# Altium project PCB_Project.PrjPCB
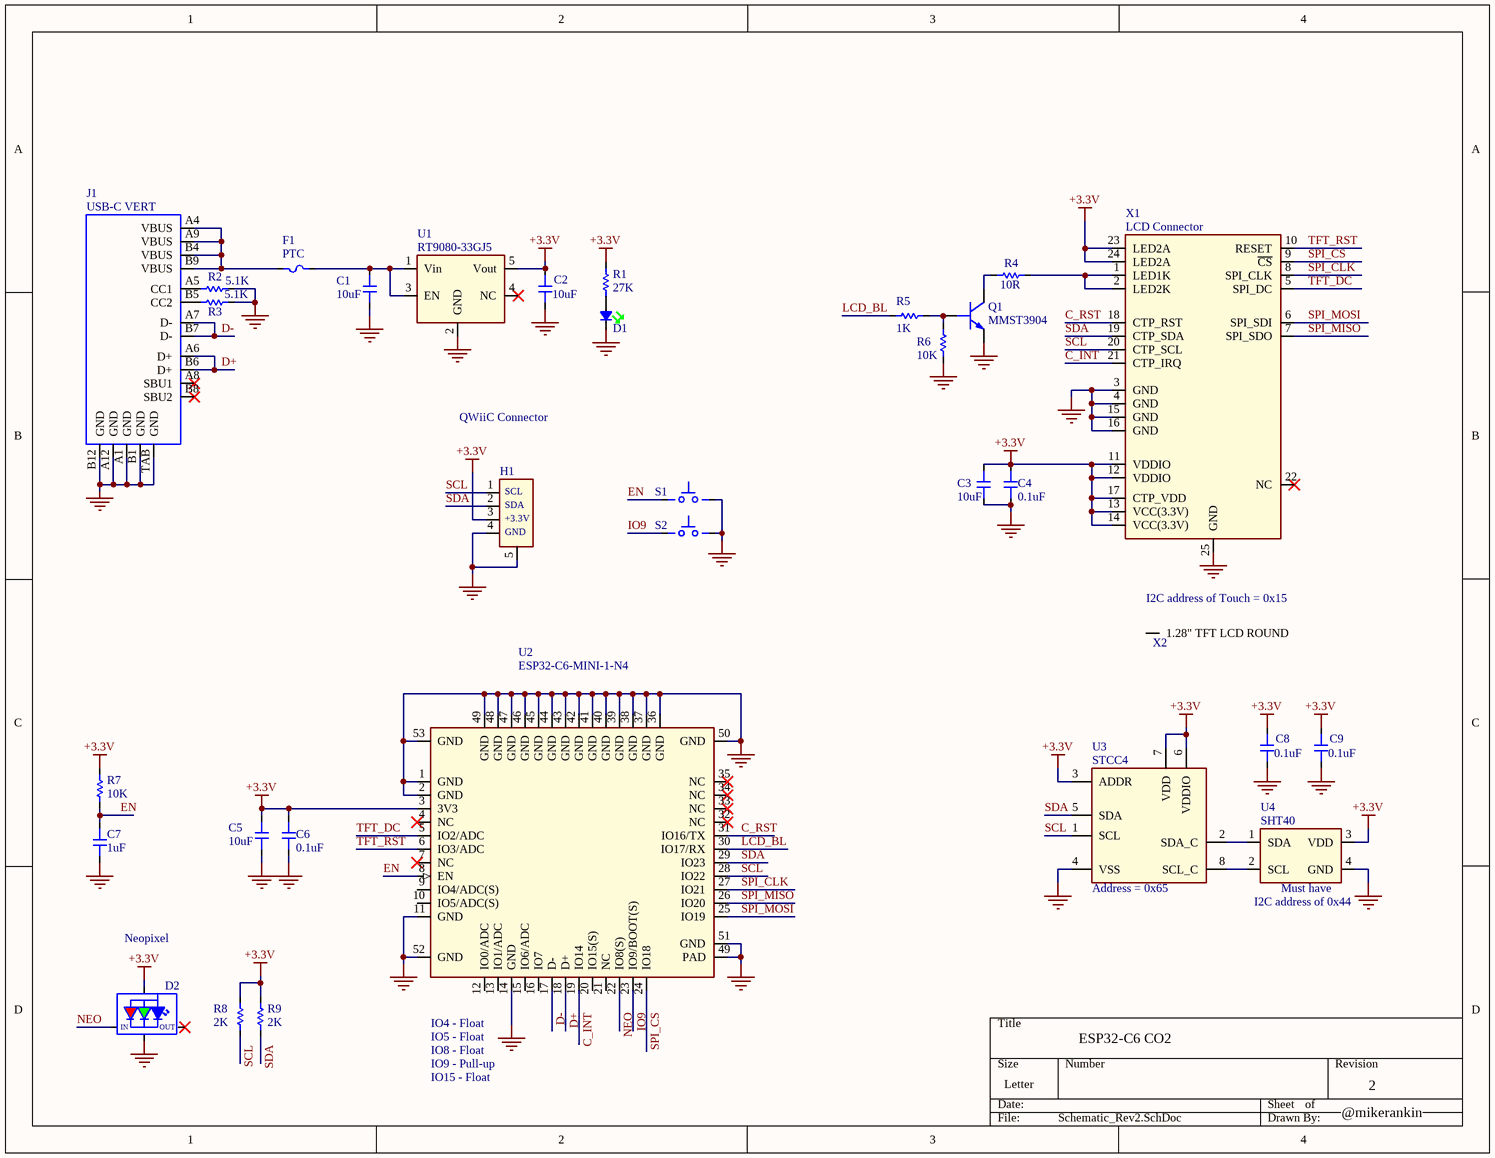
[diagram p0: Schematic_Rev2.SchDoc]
1 sheet, 32 parts. Net scope: global (net labels, ports and power ports of the same name join across sheets).
Board file: PCB_Rev2.PcbDoc

## Sheet Schematic_Rev2.SchDoc: ESP32-S3 Round Board
size Letter; Date: June 30, 2025; DrawnBy: x; Engineer: x; Address1: Mike Rankin; Address2: 0miker0@gmail.com; Address3: @mikerankin; DocumentNumber: 1; Revision: 1; SheetNumber: 1; SheetTotal: 1

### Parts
C1  10uF  [CAPC2012X140N]
C2  10uF  [CAPC2012X140N]
C3  10uF  [CAPC2012X140N]
C4  0.1uF  [CAPC1608X09L]
C5  10uF  [CAPC2012X140N]
C6  0.1uF  [CAPC1608X09L]
C7  1uF  [CAPC1005X56N]
C8  0.1uF  [CAPC1005X56N]
C9  0.1uF  [CAPC1005X56N]
D1  Green Led  [LED1005X40N-Green]  (value not drawn)
D2  RGB  [SK6805-EC14]  (value not drawn)
F1  PTC  [RESC1608X06L (0603 FOOTPRINT)]
H1  Qwiic  [HC-1.0-4PWT-B-HW]  (value not drawn)
J1  USB-C VERT  [GT-USB-8018B]
Q1  MMST3904  [SC-70]
R1  27K  [RESC1005X40L (0402 FOOTPRINT)]
R2  5.1K  [RESC1005X40L (0402 FOOTPRINT)]
R3  5.1K  [RESC1005X40L (0402 FOOTPRINT)]
R4  10R  [RESC1005X40L (0402 FOOTPRINT)]
R5  1K  [RESC1005X40L (0402 FOOTPRINT)]
R6  10K  [RESC1005X40L (0402 FOOTPRINT)]
R7  10K  [RESC1005X40L (0402 FOOTPRINT)]
R8  2K  [RESC1005X40L (0402 FOOTPRINT)]
R9  2K  [RESC1005X40L (0402 FOOTPRINT)]
S1  (no value)  [TL1015AF160QG]
S2  (no value)  [TL1015AF160QG]
U1  RT9080-33GJ5  [SOT95P280X144-5N]
U2  value ESP32-C6-MINI-1-N4  [ESP32-C6-MINI-1]  (hidden comment: ESP32-C6 MINI)
U3  STCC4  [STCC4]
U4  SHT40  [DFN-4 (1.5mm X 1.5mm)]
X1  LCD Connector  [BM10NB(0.8)-24DS-0.4V(51)]
X2  TFT_1.28 inch  (value not drawn)

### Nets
+3.3V: C2.1 C3.1 C4.1 C5.1 C6.1 C8.1 C9.1 D2.1(VDD) H1.3 R1.2 R7.2 R8.1 R9.1 U1.5(Vout) U2.3(3V3) U3.3(ADDR) U3.6(VDDIO) U3.7(VDD) U4.3(VDD) X1.11(VDDIO) X1.12(VDDIO) X1.13(VCC(3.3V)) X1.14(VCC(3.3V)) X1.17(CTP_VDD) X1.23(LED2A) X1.24(LED2A)
GND: C1.2 C2.2 C3.2 C4.2 C5.2 C6.2 C7.2 C8.2 C9.2 D1.1 D2.3(GND) H1.4 H1.5 J1.A1(GND) J1.A12(GND) J1.B1(GND) J1.B12(GND) J1.TAB(GND) Q1.2(E) R2.1 R3.1 R6.2 S1.2(B) S2.2(B) U1.2(GND) U2.1(GND) U2.2(GND) U2.11(GND) U2.14(GND) U2.36(GND) U2.37(GND) U2.38(GND) U2.39(GND) U2.40(GND) U2.41(GND) U2.42(GND) U2.43(GND) U2.44(GND) U2.45(GND) U2.46(GND) U2.47(GND) U2.48(GND) U2.49(GND) U2.50(GND) U2.51(GND) U2.52(GND) U2.53(GND) U3.4(VSS) U4.4(GND) X1.3(GND) X1.4(GND) X1.15(GND) X1.16(GND) X1.25(GND)
C_INT: U2.19(IO14) X1.21(CTP_IRQ)
C_RST: U2.31(IO16/TX) X1.18(CTP_RST)
D+: J1.A6(D+) J1.B6(D+) U2.18(D+)
D-: J1.A7(D-) J1.B7(D-) U2.17(D-)
EN: C7.1 R7.1 S1.1(A) U2.8(EN)
IO9: S2.1(A) U2.23(IO9/BOOT(S))
LCD_BL: R5.2 U2.30(IO17/RX)
NEO: D2.4(DIN) U2.22(IO8(S))
SCL: H1.1 R8.2 U2.28(IO22) U3.1(SCL) X1.20(CTP_SCL)
SDA: H1.2 R9.2 U2.29(IO23) U3.5(SDA) X1.19(CTP_SDA)
SPI_CLK: U2.27(IO21) X1.8(SPI_CLK)
SPI_CS: U2.24(IO18) X1.9(~{CS})
SPI_MISO: U2.26(IO20) X1.7(SPI_SDO)
SPI_MOSI: U2.25(IO19) X1.6(SPI_SDI)
TFT_DC: U2.5(IO2/ADC) X1.5(SPI_DC)
TFT_RST: U2.6(IO3/ADC) X1.10(RESET)
NetC1_1: C1.1 F1.1 U1.1(Vin) U1.3(EN)
NetD1_2: D1.2 R1.1
NetF1_2: F1.2 J1.A4(VBUS) J1.A9(VBUS) J1.B4(VBUS) J1.B9(VBUS)
NetJ1_A5: J1.A5(CC1) R2.2
NetJ1_B5: J1.B5(CC2) R3.2
NetQ1_1: Q1.1(B) R5.1 R6.1
NetQ1_3: Q1.3(C) R4.2
NetR4_1: R4.1 X1.1(LED1K) X1.2(LED2K)
NetU3_2: U3.2(SDA_C) U4.1(SDA)
NetU3_8: U3.8(SCL_C) U4.2(SCL)

Not connected (* = marked no-connect by the designer): D2 2(DOUT)*; J1 A8(SBU1)* B8(SBU2)*; U1 4(NC)*; U2 4(NC)* 7(NC)* 9(IO4/ADC(S)) 10(IO5/ADC(S)) 12(IO0/ADC) 13(IO1/ADC) 15(IO6/ADC) 16(IO7) 20(IO15(S)) 21(NC) 32(NC)* 33(NC)* 34(NC)* 35(NC)*; X1 22(NC)*; X2 1(1.28"_TFT_LCD_ROUND)

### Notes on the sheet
- QWiiC Connector
- (near X2) I2C address of Touch = 0x15
- (near U4) I2C address of 0x44
- (near U4) Must have
- (near D2) Neopixel
- ESP32-C6 CO2 Monitor
- 2
- @mikerankin

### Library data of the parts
C1 C2 C5 = CAP_0805: CAP 10uF 50V 0805; Part_Footprint: 0805
C3 = CAP_0805: CAP 10uF 0805; Part_Footprint: 0805
C4 C6 = CAP_0603: CAP 0.1uF 0603; Part_Footprint: 0603
C7 = CAP_0402: CAP 1uF 0402; Part_Footprint: 0402
C8 C9 = CAP_0402: CAP 0.1uF 0402; Part_Footprint: 0402
D1 = LED_0402_SMALL_GREEN: LED Green 0402; Part_Number: C74338; Part_Footprint: 0402; Vendor: LCSC
D2 = SK6805-EC14: LED,RGB,NEOPIXEL,SK6805-EC14; Part_Number: C2909055; Manufacturer: OPSCO; Vendor: LCSC
F1 = PTC_FUSE_0603: PTC FUSE 0.5mA hold, 1A trip 0603; Manufacturer: JDT Fuse; Part_Number: C2982257; Part_Footprint: 0603; Vendor: LCSC
H1 = HC-1.0-4PWT-B-HW: CONN HEADER 4POS .100 R/A QWIIC; Manufacturer: HCTL; Part_Number: C19270571; Vendor: LCSC
J1 = USB-C_VERT_TH_MOUNT_RIDGID: CONN RECPT USB-C Vertical w/TH Mount; Manufacturer: G-Switch; Part_Footprint: SMT; Vendor: LCSC
Q1 = MMST3904: TRANSISTOR NPN GP 40V SC-70; Manufacturer: Changjiang; Part_Number: C54879; Vendor: LCSC
R1 = RES_0402: RES 27K 0402; Part_Footprint: 0402
R2 R3 = RES_0402: RES 5.1K 0402; Part_Footprint: 0402
R4 = RES_0402: RES 10R 0402; Part_Footprint: 0402
R5 = RES_0402: RES 1K 0402; Part_Footprint: 0402
R6 R7 = RES_0402: RES 10K 0402; Part_Footprint: 0402
R8 R9 = RES_0402: RES 2K 0402; Part_Footprint: 0402
S1 S2 = TL1015AF160QG: SWITCH MOMENTARY; Part_Footprint: SMD; Vendor: Digi-Key
U1 = RT9080-33GJ5: IC LDO 3.3V 0.6A SOT23-5; Manufacturer: Richtek Tech; Part_Number: C841192; Vendor: LCSC
U2 = ESP32-C6-MINI-1-N4: WIFI/Bluetooth, 4M Flash  QFN-56 7x7; Manufacturer: Espressif; Part_Number: C5736265; Part_Footprint: SMD-41P; Vendor: LCSC
U3 = STCC4: CO2 SENSOR I2C SMD; Manufacturer: Sensirion; Part_Number: STCC4-D-R3; Part_Footprint: SMT; Vendor: Digi-Key
U4 = SHT40: Sensor Humidity/Temperature I2C SMD; Manufacturer: Sensirion AG; Part_Footprint: 6-DFN; Part_Number: SHT40-AD1B; Vendor: Digi-Key
X1 = FFC, FPC 24 pin 0.5mm Con 1.28" TFT: FFC, FPC 24 pin 0.4mm Connector for 1.28" TFT; Manufacturer: Hirose; Part_Footprint: SMD; Vendor: Digi-Key
X2 = TFT_GLASS 1.28 Inch Round: 1.28 INCH TFT GLASS ROUND; Part_Number: ER-TFT1.28-2; Manufacturer: BuyDisplay; Value: 1.28" Round LCD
